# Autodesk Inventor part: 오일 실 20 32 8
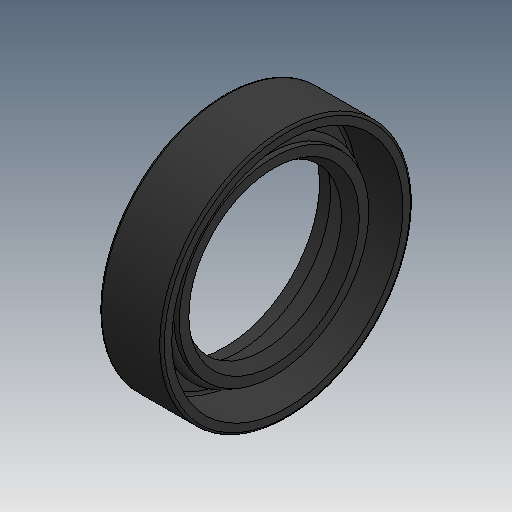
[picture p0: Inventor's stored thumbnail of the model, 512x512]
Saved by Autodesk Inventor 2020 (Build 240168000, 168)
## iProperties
Created: 2024-11
Part Number: 오일 실 20 32 8
Material: 고무
Description: 오일-실
Document SubType Name: Modeling
Designer: shin
Density: 0.93 g/cm^3
Appearance: 기본값
Author: jhkim
Sending System: Autodesk Inventor 2025
Preprocessor: ST-DEVELOPER v20
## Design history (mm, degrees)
feature "Solid1"
node "솔리드1"
